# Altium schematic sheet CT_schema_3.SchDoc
size 461 x 327 mm
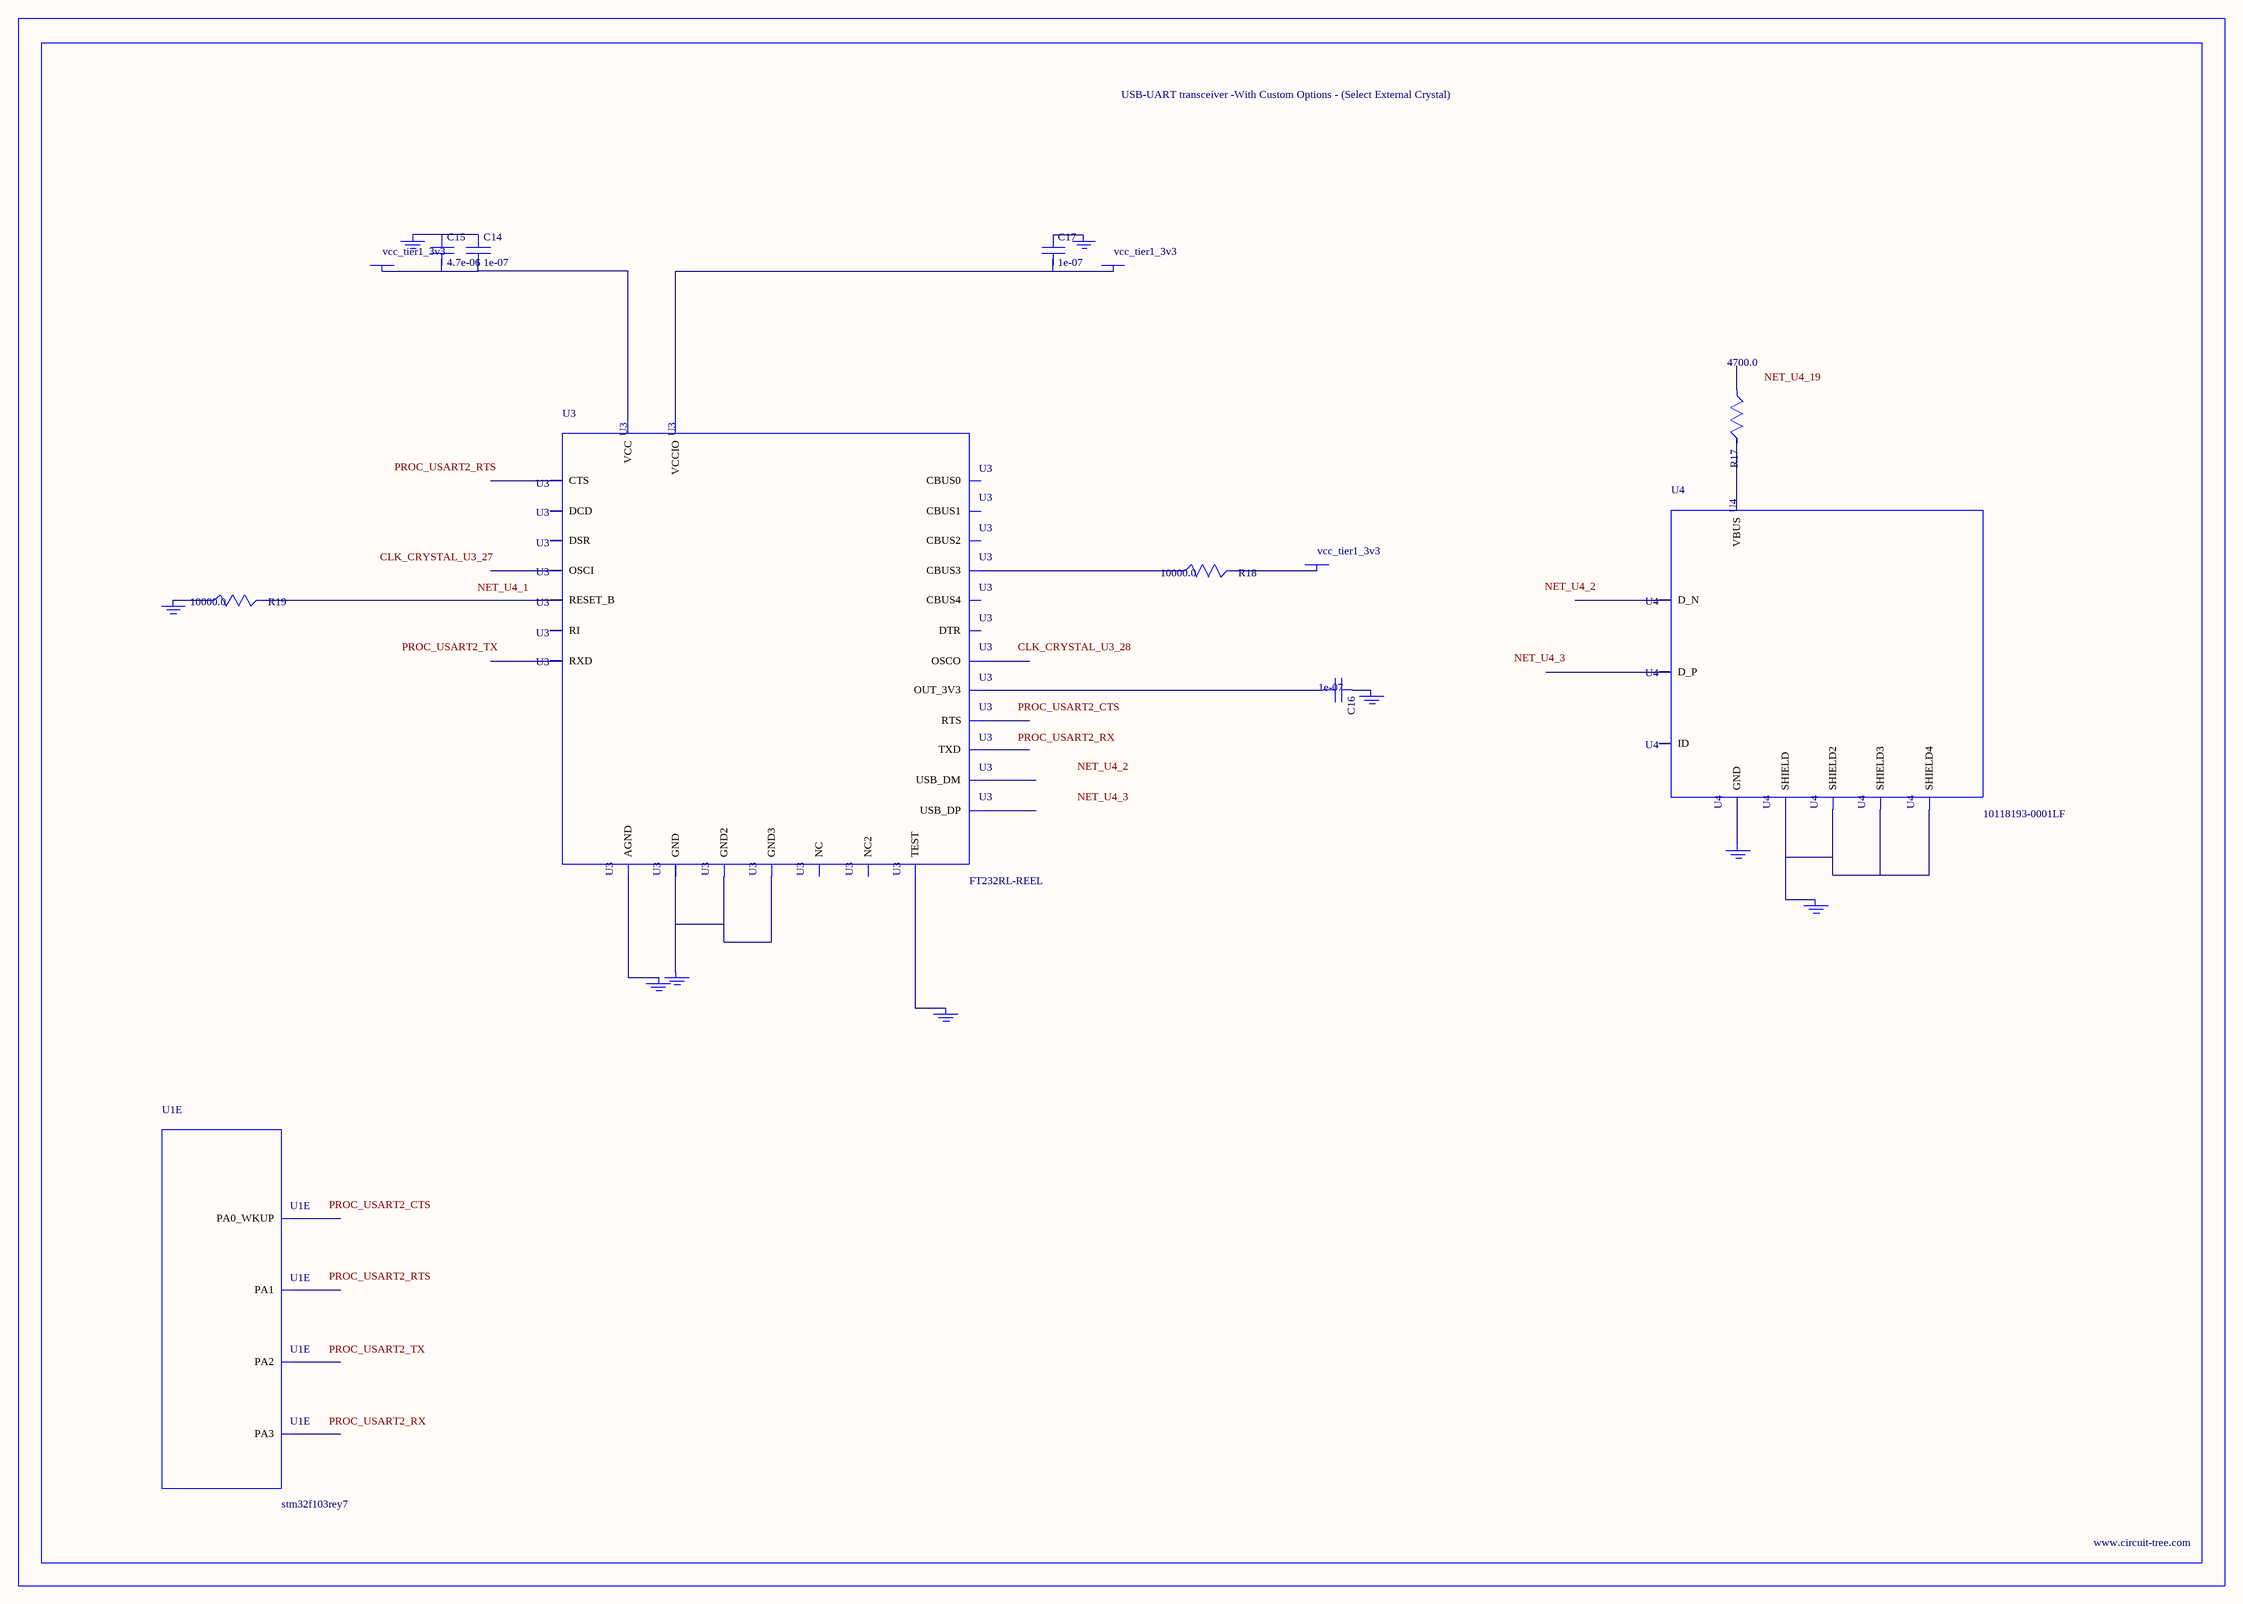
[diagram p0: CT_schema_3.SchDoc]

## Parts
BORDER2  (no value)
C14  1e-07  [C0402]
C15  4.7e-06  [C0805]
C16  1e-07  [C0402]
C17  1e-07  [C0402]
GND_INSTANCE_2_0  (no value)
GND_INSTANCE_2_1  (no value)
GND_INSTANCE_2_2  (no value)
GND_INSTANCE_2_3  (no value)
GND_INSTANCE_2_4  (no value)
GND_INSTANCE_2_5  (no value)
GND_INSTANCE_2_6  (no value)
GND_INSTANCE_2_7  (no value)
GND_INSTANCE_2_8  (no value)
POWER_INSTANCE_2_0  vcc_tier1_3v3
POWER_INSTANCE_2_1  vcc_tier1_3v3
POWER_INSTANCE_2_2  vcc_tier1_3v3
R17  4700.0  [R0603]
R18  10000.0  [R0603]
R19  10000.0  [R0603]
U1  stm32f103rey7  [WLCSP64]  (part E of 6)
U3  FT232RL-REEL  [SSOP-28]
U4  10118193-0001LF  [FCI_10118193-0001LF]

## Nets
NetC14_1: C14.1 C15.1 GND_INSTANCE_2_3.0(GND)
NetC14_2: C14.2 C15.2 POWER_INSTANCE_2_2.0(PWR) U3.20(VCC)
NetC16_1: C16.1 GND_INSTANCE_2_1.0(GND)
NetC16_2: C16.2 U3.17(OUT_3V3)
NetC17_1: C17.1 GND_INSTANCE_2_0.0(GND)
NetC17_2: C17.2 POWER_INSTANCE_2_0.0(PWR) U3.4(VCCIO)
NetGND_INSTANCE_2_2_0: GND_INSTANCE_2_2.0(GND) R19.1
NetGND_INSTANCE_2_4_0: GND_INSTANCE_2_4.0(GND) U3.25(AGND)
NetGND_INSTANCE_2_5_0: GND_INSTANCE_2_5.0(GND) U3.26(TEST)
NetGND_INSTANCE_2_6_0: GND_INSTANCE_2_6.0(GND) U3.7(GND) U3.18(GND2) U3.21(GND3)
NetGND_INSTANCE_2_7_0: GND_INSTANCE_2_7.0(GND) U4.6(SHIELD) U4.7(SHIELD2) U4.8(SHIELD3) U4.9(SHIELD4)
NetGND_INSTANCE_2_8_0: GND_INSTANCE_2_8.0(GND) U4.5(GND)
NetPOWER_INSTANCE_2_1_0: POWER_INSTANCE_2_1.0(PWR) R18.2
NetR17_2: R17.2 U4.1(VBUS)
NetR18_1: R18.1 U3.14(CBUS3)
NetR19_2: R19.2 U3.19(RESET_B)

Not connected (* = marked no-connect by the designer): R17 1; U1 E6(PA1) F6(PA0_WKUP) G7(PA3) H8(PA2); U3 1(TXD) 2(DTR) 3(RTS) 5(RXD) 6(RI) 8(NC) 9(DSR) 10(DCD) 11(CTS) 12(CBUS4) 13(CBUS2) 15(USB_DP) 16(USB_DM) 22(CBUS1) 23(CBUS0) 24(NC2) 27(OSCI) 28(OSCO); U4 2(D_N) 3(D_P) 4(ID)

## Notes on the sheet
- Labels drawn without touching a wire or pin: CLK_CRYSTAL_U3_27, CLK_CRYSTAL_U3_28, NET_U4_1, NET_U4_2, NET_U4_3, NET_U4_19, PROC_USART2_CTS, PROC_USART2_RTS, PROC_USART2_RX, PROC_USART2_TX

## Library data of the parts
BORDER2 = BORDER_PAGE2
C14 C16 C17 = C0402C104K3RACTU
C15 = C0805C475K4RACTU
GND_INSTANCE_2_0-GND_INSTANCE_2_8 = GND
POWER_INSTANCE_2_0-POWER_INSTANCE_2_2 = PWR
R17 = RC0603JR-074K7L
R18 R19 = RC0603JR-0710KL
